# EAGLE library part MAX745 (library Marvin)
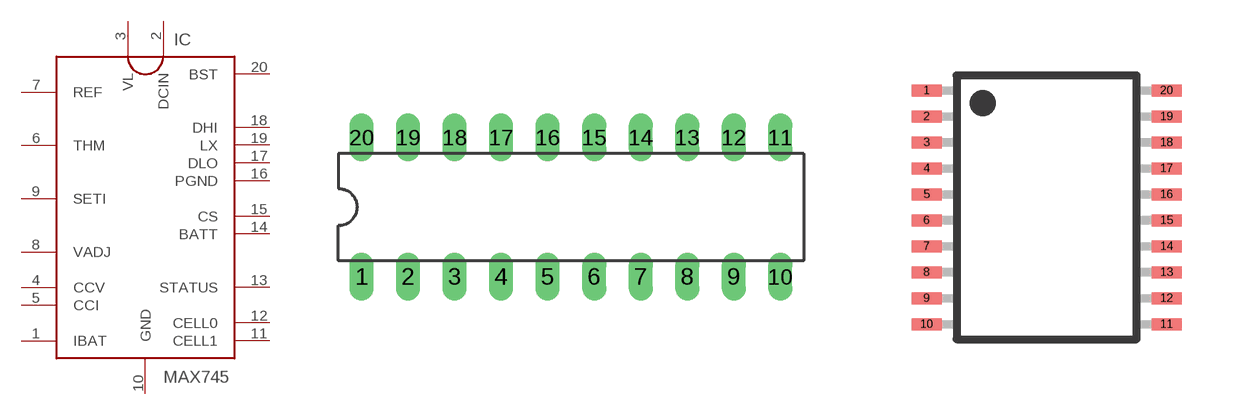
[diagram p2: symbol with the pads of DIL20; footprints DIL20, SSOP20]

Designator prefix IC

## MAX745D  [DIL20]
1  IBAT
2  DCIN
3  VL
4  CCV
5  CCI
6  THM
7  REF
8  VADJ
9  SETI
10  GND
11  CELL1
12  CELL0
13  STATUS
14  BATT
15  CS
16  PGND
17  DLO
18  DHI
19  LX
20  BST

## MAX745S  [SSOP20]
Pads as for DIL20

## Footprint DIL20 (pad centres in mm)
drill 0.813 long: 1 -11.43,-3.81; 2 -8.89,-3.81; 3 -6.35,-3.81; 4 -3.81,-3.81; 5 -1.27,-3.81; 6 1.27,-3.81; 7 3.81,-3.81; 8 6.35,-3.81; 9 8.89,-3.81; 10 11.43,-3.81; 11 11.43,3.81; 12 8.89,3.81; 13 6.35,3.81; 14 3.81,3.81; 15 1.27,3.81; 16 -1.27,3.81; 17 -3.81,3.81; 18 -6.35,3.81; 19 -8.89,3.81; 20 -11.43,3.81

## Footprint SSOP20 (pad centres in mm)
smd 0.75 x 0.3: 1 -3.032,2.973; 2 -3.032,2.323; 3 -3.032,1.673; 4 -3.032,1.023; 5 -3.032,0.373; 6 -3.032,-0.277; 7 -3.032,-0.927; 8 -3.032,-1.577; 9 -3.032,-2.227; 10 -3.032,-2.877; 11 2.968,-2.877; 12 2.968,-2.227; 13 2.968,-1.577; 14 2.968,-0.927; 15 2.968,-0.277; 16 2.968,0.373; 17 2.968,1.023; 18 2.968,1.673; 19 2.968,2.323; 20 2.968,2.973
